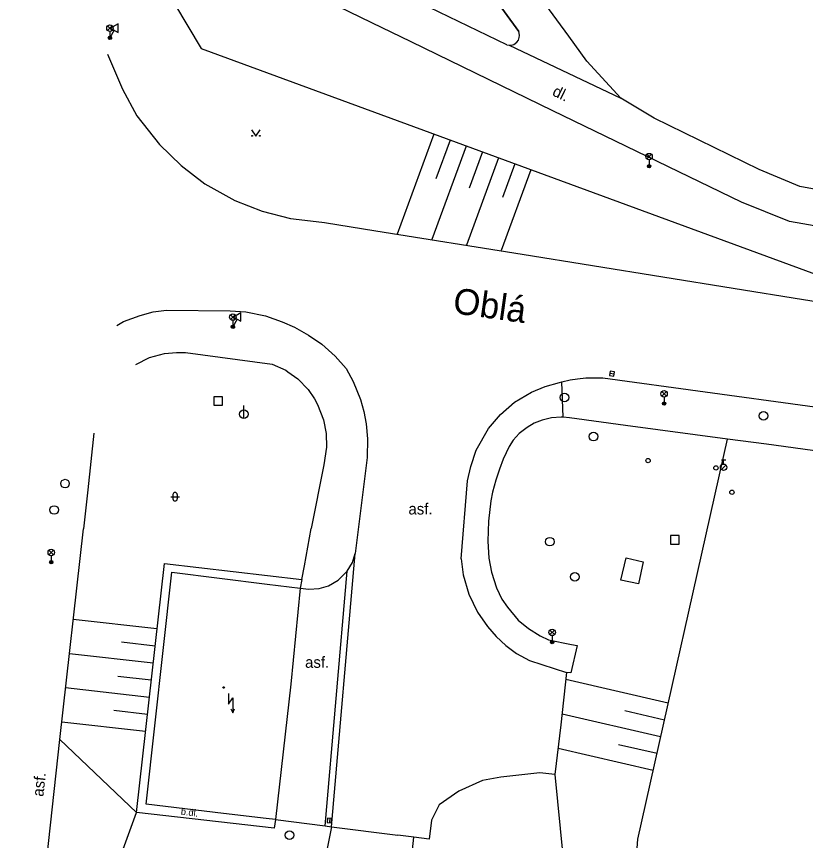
# Model space of a CAD drawing. Extents: x -602419 to -601554, y -1162937 to -1162362.
# Drawn here: x -602029.87 to -601984.03, y -1162678.29 to -1162630.44 of the extents above; entities that cross this region are included whole.
import ezdxf

# ---------------------------------------------------------------- set-up
doc = ezdxf.new("R2010")
doc.units = 0
doc.layers.add('Podklad', color=7, linetype='Continuous')

msp = doc.modelspace()

# ---------------------------------------------------------------- linework, layer by layer
at = {"layer": 'Podklad'}
for p, q in [((-602024.5725, -1162631.25), (-602024.3075, -1162630.985)), ((-602024.5725, -1162630.985), (-602024.3075, -1162631.25)), ((-602024.1855, -1162631.2392), (-602024.44, -1162631.68)), ((-602024.44, -1162631.305), (-602024.44, -1162631.68)), ((-602024.5483, -1162631.6175), (-602024.3317, -1162631.7425)), ((-601993.2525, -1162638.71), (-601992.9875, -1162638.445)), ((-601993.2525, -1162638.445), (-601992.9875, -1162638.71)), ((-601993.12, -1162638.765), (-601993.12, -1162639.14)), ((-602017.4325, -1162648.03), (-602017.1675, -1162647.765)), ((-602017.4325, -1162647.765), (-602017.1675, -1162648.03)), ((-602017.0455, -1162648.0192), (-602017.3, -1162648.46)), ((-602017.3, -1162648.085), (-602017.3, -1162648.46)), ((-602017.4083, -1162648.3975), (-602017.1917, -1162648.5225)), ((-601995.3937, -1162651.1622), (-601995.1463, -1162651.1978)), ((-601992.3825, -1162652.49), (-601992.1175, -1162652.225)), ((-601992.3825, -1162652.225), (-601992.1175, -1162652.49)), ((-601992.25, -1162652.545), (-601992.25, -1162652.92)), ((-602016.6599, -1162653.78), (-602016.6599, -1162653.03)), ((-602025.38, -1162654.64), (-602025.7199, -1162657.93)), ((-601988.915, -1162656.1825), (-601988.665, -1162656.1825)), ((-601988.79, -1162656.4325), (-601988.79, -1162656.1825)), ((-601988.919, -1162656.756), (-601988.654, -1162656.491)), ((-602020.903, -1162658.328), (-602020.403, -1162658.328)), ((-602020.778, -1162658.203), (-602020.778, -1162658.453)), ((-602020.528, -1162658.203), (-602020.528, -1162658.453)), ((-602027.9825, -1162661.7), (-602027.7175, -1162661.435)), ((-602027.9825, -1162661.435), (-602027.7175, -1162661.7)), ((-602027.85, -1162661.755), (-602027.85, -1162662.13)), ((-601998.8825, -1162666.34), (-601998.6175, -1162666.075)), ((-601998.8825, -1162666.075), (-601998.6175, -1162666.34)), ((-601998.75, -1162666.395), (-601998.75, -1162666.77)), ((-602011.6708, -1162677.0053), (-602011.6892, -1162677.2547))]:
    msp.add_line(p, q, dxfattribs=at)
for points in [[(-602024.45, -1162623.4), (-602019.15, -1162632.31), (-601975.87, -1162648.2)], [(-602009.2199, -1162630.81), (-602022.88, -1162624.18)], [(-602000.69, -1162631.32), (-602003.71, -1162627.1599)], [(-602003.71, -1162627.1599), (-602000.69, -1162631.32)], [(-601997.78, -1162631.59), (-602000.3, -1162628.14)], [(-602001.39, -1162632.08), (-602006.44, -1162629.65)], [(-602006.94, -1162631.92), (-602009.2199, -1162630.81)], [(-602001.39, -1162632.08), (-602001.25, -1162632.11), (-602001.11, -1162632.1), (-602000.9699, -1162632.06), (-602000.8, -1162631.93), (-602000.71, -1162631.81), (-602000.6599, -1162631.67), (-602000.64, -1162631.55), (-602000.6599, -1162631.4099), (-602000.69, -1162631.32)], [(-601998.71, -1162635.92), (-602006.94, -1162631.92)], [(-601982.56, -1162640.65), (-601984.36, -1162640.32), (-601986.73, -1162639.33), (-601992.83, -1162636.34), (-601994.76, -1162635.18), (-601996.73, -1162633.03), (-601997.78, -1162631.59)], [(-602001.25, -1162632.11), (-601994.76, -1162635.18)], [(-602024.58, -1162632.64), (-602023.7199, -1162634.6599), (-602022.88, -1162636.21), (-602021.56, -1162637.87), (-602020.31, -1162639.1), (-602018.92, -1162640.17), (-602017.19, -1162641.12), (-602015.6, -1162641.74), (-602013.95, -1162642.17), (-602012.46, -1162642.35), (-602011.9699, -1162642.4)], [(-601983.08, -1162642.68), (-601984.96, -1162642.34), (-601987.76, -1162641.23), (-601998.71, -1162635.92)], [(-602016.21, -1162637.025), (-602015.96, -1162637.4), (-602015.71, -1162637.025)], [(-602005.62, -1162637.28), (-602007.75, -1162643.08)], [(-602004.68, -1162637.62), (-602005.5, -1162639.87)], [(-602003.74, -1162637.9699), (-602005.74, -1162643.4)], [(-602001.86, -1162638.6599), (-602003.7199, -1162643.7199)], [(-602002.8, -1162638.31), (-602003.57, -1162640.4099)], [(-602000.92, -1162639), (-602001.64, -1162640.95)], [(-601999.99, -1162639.35), (-602001.71, -1162644.04)], [(-602011.9699, -1162642.4), (-602009, -1162642.88)], [(-602009, -1162642.88), (-602000.49, -1162644.24)], [(-602000.49, -1162644.24), (-601984.15, -1162646.87)], [(-601984.15, -1162646.87), (-601975.87, -1162648.2)], [(-602024.04, -1162648.38), (-602023.6599, -1162648.15), (-602022.69, -1162647.8), (-602021.92, -1162647.6), (-602021.1599, -1162647.5)], [(-602021.1599, -1162647.5), (-602017.45, -1162647.54)], [(-602017.45, -1162647.54), (-602016.55, -1162647.6), (-602015.4099, -1162647.83), (-602014.43, -1162648.18), (-602013.7199, -1162648.49), (-602013.4569, -1162648.6343), (-602012.9, -1162648.94), (-602012.13, -1162649.48), (-602011.35, -1162650.17), (-602010.71, -1162650.89), (-602010.31, -1162651.63), (-602009.89, -1162652.68), (-602009.7, -1162653.38), (-602009.56, -1162654.09), (-602009.4699, -1162654.96), (-602009.5, -1162656.06)], [(-602022.93, -1162650.65), (-602022.15, -1162650.24), (-602021.28, -1162650.01), (-602020.58, -1162649.95), (-602020.05, -1162649.96)], [(-602020.05, -1162649.96), (-602015.02, -1162650.63)], [(-602015.02, -1162650.63), (-602014.23, -1162650.99), (-602014.108, -1162651.0771), (-602013.53, -1162651.49), (-602012.92, -1162652.11), (-602012.55, -1162652.64), (-602012.39, -1162652.9699), (-602012.04, -1162653.87), (-602011.87, -1162654.65), (-602011.86, -1162655.46), (-602012.02, -1162656.4699)], [(-602003.6599, -1162657.4099), (-602003.48, -1162656.57), (-602003.17, -1162655.62), (-602002.45, -1162654.37), (-602001.75, -1162653.55), (-602000.94, -1162652.84), (-601999.96, -1162652.26), (-601999.1599, -1162651.93), (-601998.33, -1162651.7), (-601998.1862, -1162651.6658), (-601997.7, -1162651.55), (-601997.2688, -1162651.4884), (-601996.79, -1162651.42), (-601995.8, -1162651.42)], [(-601995.8, -1162651.42), (-601983.9133, -1162653.0562), (-601972.9094, -1162654.571)], [(-601998.1199, -1162653.7185), (-601998.1862, -1162651.6658)], [(-601997.75, -1162653.75), (-601998.1199, -1162653.7185), (-601998.2199, -1162653.71), (-601998.79, -1162653.75), (-601999.33, -1162653.89), (-601999.79, -1162654.06), (-602000.21, -1162654.31), (-602000.6599, -1162654.6599), (-602001.01, -1162655.05), (-602001.25, -1162655.4099), (-602001.59, -1162656.15), (-602001.81, -1162656.73), (-602002.02, -1162657.36), (-602002.21, -1162658.07), (-602002.31, -1162658.57), (-602002.45, -1162659.74), (-602002.48, -1162660.92), (-602002.42, -1162661.9), (-602002.28, -1162662.7199), (-602001.99, -1162663.63), (-602001.67, -1162664.27), (-602001.35, -1162664.75), (-602000.73, -1162665.49), (-602000.12, -1162665.98), (-601999.45, -1162666.4), (-601998.96, -1162666.64)], [(-601988.57, -1162654.98), (-601994.49, -1162654.19), (-601997.75, -1162653.75)], [(-601928.54, -1162694.32), (-601947.71, -1162697.88), (-601984.32, -1162697.95), (-601986.89, -1162696.1), (-601988.58, -1162694.52), (-601989.65, -1162693.28), (-601989.95, -1162692.89), (-601990.81, -1162691.65), (-601991.85, -1162689.83), (-601993.05, -1162686.96), (-601993.69, -1162684.25), (-601993.99, -1162681.09), (-601993.78, -1162678.2199), (-601988.57, -1162654.98)], [(-601986.29, -1162655.28), (-601988.57, -1162654.98)], [(-601983.0609, -1162655.7135), (-601986.29, -1162655.28)], [(-602009.5, -1162656.06), (-602010.19, -1162661.62)], [(-602012.02, -1162656.4699), (-602012.75, -1162660.18)], [(-602004.04, -1162661.93), (-602003.6599, -1162657.4099)], [(-602025.7199, -1162657.93), (-602025.98, -1162660.19)], [(-602027.35, -1162672.42), (-602025.98, -1162660.19)], [(-602013.14, -1162662.35), (-602012.75, -1162660.18)], [(-602011.56, -1162677.49), (-602010.19, -1162661.62)], [(-602010.65, -1162662.65), (-602010.35, -1162662.14), (-602010.19, -1162661.62)], [(-602004.04, -1162661.93), (-602003.92, -1162662.87), (-602003.59, -1162663.99), (-602003.08, -1162665.03), (-602002.51, -1162665.86), (-602002, -1162666.44), (-602001.44, -1162666.9699), (-602000.82, -1162667.43), (-602000.07, -1162667.85)], [(-601994.46, -1162661.87), (-601993.46, -1162662.11), (-601993.73, -1162663.39), (-601994.76, -1162663.17), (-601994.46, -1162661.87)], [(-602022.9, -1162676.6599), (-602021.28, -1162662.2), (-602013.3, -1162663.14)], [(-602013.3, -1162663.14), (-602013.14, -1162662.35)], [(-602022.34, -1162676.19), (-602020.84, -1162662.7199)], [(-602020.84, -1162662.7199), (-602015.3, -1162663.4)], [(-602013.38, -1162663.64), (-602012.89, -1162663.7), (-602012.28, -1162663.6599), (-602011.74, -1162663.5), (-602011.18, -1162663.18), (-602010.65, -1162662.65)], [(-602011.93, -1162677.44), (-602010.65, -1162662.65)], [(-602015.3, -1162663.4), (-602013.38, -1162663.64)], [(-602013.3, -1162663.14), (-602013.38, -1162663.64)], [(-602013.38, -1162663.64), (-602013.94, -1162669.21)], [(-602021.71, -1162666), (-602026.57, -1162665.46)], [(-602021.82, -1162667), (-602023.76, -1162666.78)], [(-601998.96, -1162666.64), (-601997.62, -1162666.9099), (-601997.3, -1162666.9699), (-601997.6599, -1162668.56), (-601997.9099, -1162668.53)], [(-602021.93, -1162667.99), (-602026.79, -1162667.45)], [(-602000.07, -1162667.85), (-601997.9099, -1162668.53)], [(-602022.04, -1162668.98), (-602023.99, -1162668.77)], [(-601997.9099, -1162668.53), (-601998.24, -1162671.58), (-601998.59, -1162674.46)], [(-602013.94, -1162669.21), (-602014.83, -1162677.07)], [(-601992.01, -1162670.32), (-601997.95, -1162668.95)], [(-602022.15, -1162669.98), (-602027.02, -1162669.43)], [(-602017.56, -1162669.76), (-602017.56, -1162670.385), (-602017.31, -1162670.01), (-602017.31, -1162670.885)], [(-602022.26, -1162670.9699), (-602024.21, -1162670.75)], [(-602017.4195, -1162670.6405), (-602017.31, -1162670.885), (-602017.2005, -1162670.6405)], [(-601992.23, -1162671.3), (-601994.53, -1162670.76)], [(-601992.45, -1162672.27), (-601998.17, -1162670.95)], [(-602022.37, -1162671.9699), (-602027.24, -1162671.42)], [(-602029.87, -1162695.42), (-602028.77, -1162685.4), (-602027.35, -1162672.42)], [(-602027.35, -1162672.42), (-602022.9, -1162676.6599)], [(-601992.88, -1162674.2199), (-601998.4099, -1162672.95)], [(-601992.6599, -1162673.24), (-601994.89, -1162672.73)], [(-601998.59, -1162674.46), (-601999.46, -1162674.36), (-602001.74, -1162674.62), (-602002.79, -1162674.8), (-602004.18, -1162675.42), (-602005.31, -1162676.23), (-602005.76, -1162677.11), (-602005.9, -1162678.21), (-602006.7841, -1162678.0983), (-602007.7199, -1162677.98)], [(-601998.59, -1162674.46), (-601997.1599, -1162688.95), (-601990.98, -1162701.28)], [(-602017.84, -1162676.7199), (-602022.34, -1162676.19)], [(-602021.77, -1162698.83), (-602022.75, -1162698.11), (-602023.56, -1162695.49), (-602024, -1162693.13), (-602023.97, -1162689.98), (-602025.58, -1162684.06), (-602022.9, -1162676.66)], [(-602014.83, -1162677.07), (-602014.9, -1162677.58), (-602022.9, -1162676.6599)], [(-602015.37, -1162677.01), (-602017.84, -1162676.7199)], [(-602014.83, -1162677.07), (-602015.37, -1162677.01)], [(-602014.83, -1162677.07), (-602011.93, -1162677.44)], [(-602011.93, -1162677.44), (-602011.56, -1162677.49)], [(-602011.56, -1162677.49), (-602013.02, -1162684.72)], [(-602011.56, -1162677.49), (-602007.7199, -1162677.98)], [(-602007.5488, -1162685.3648), (-602007.533, -1162685.2149), (-602006.7841, -1162678.0983)]]:
    msp.add_lwpolyline(points, dxfattribs=at)
for points in [[(-602024.402, -1162631.1142), (-602023.969, -1162631.3642), (-602023.969, -1162630.8642)], [(-602017.262, -1162647.8942), (-602016.829, -1162648.1442), (-602016.829, -1162647.6442)], [(-601995.4115, -1162651.2859), (-601995.1641, -1162651.3215), (-601995.1285, -1162651.0741), (-601995.3759, -1162651.0385)], [(-602018.4, -1162653.02), (-602017.9, -1162653.02), (-602017.9, -1162652.52), (-602018.4, -1162652.52)], [(-601991.88, -1162661.08), (-601991.38, -1162661.08), (-601991.38, -1162660.58), (-601991.88, -1162660.58)], [(-602011.7955, -1162676.9962), (-602011.8138, -1162677.2455), (-602011.5645, -1162677.2638), (-602011.5462, -1162677.0145)]]:
    msp.add_lwpolyline(points, close=True, dxfattribs=at)
for centre, radius in [((-602024.44, -1162631.1175), 0.1875), ((-602024.44, -1162631.68), 0.1), ((-602024.44, -1162631.68), 0.0723), ((-602024.44, -1162631.68), 0.0438), ((-602016.1851, -1162637.3749), 0.025), ((-602015.7354, -1162637.3749), 0.025), ((-601993.12, -1162638.5775), 0.1875), ((-601993.12, -1162639.14), 0.1), ((-601993.12, -1162639.14), 0.0723), ((-601993.12, -1162639.14), 0.0438), ((-602017.3, -1162647.8975), 0.1875), ((-602017.3, -1162648.46), 0.1), ((-602017.3, -1162648.46), 0.0723), ((-602017.3, -1162648.46), 0.0438), ((-601998.03, -1162652.57), 0.25), ((-601992.25, -1162652.3575), 0.1875), ((-601992.25, -1162652.92), 0.1), ((-601992.25, -1162652.92), 0.0723), ((-601992.25, -1162652.92), 0.0438), ((-602016.6599, -1162653.53), 0.25), ((-601986.48, -1162653.63), 0.25), ((-601996.35, -1162654.84), 0.25), ((-601993.18, -1162656.23), 0.125), ((-601989.24, -1162656.6599), 0.125), ((-601988.79, -1162656.62), 0.1875), ((-602027.05, -1162657.57), 0.25), ((-601988.31, -1162658.07), 0.125), ((-602027.68, -1162659.1), 0.25), ((-601998.88, -1162660.94), 0.25), ((-602027.85, -1162661.5675), 0.1875), ((-602027.85, -1162662.13), 0.1), ((-602027.85, -1162662.13), 0.0723), ((-602027.85, -1162662.13), 0.0438), ((-601997.43, -1162662.98), 0.25), ((-601998.75, -1162666.2075), 0.1875), ((-601998.75, -1162666.77), 0.1), ((-601998.75, -1162666.77), 0.0723), ((-601998.75, -1162666.77), 0.0438), ((-602017.83, -1162669.4099), 0.045), ((-602017.83, -1162669.4099), 0.0199), ((-602014.01, -1162677.98), 0.25)]:
    msp.add_circle(centre, radius, dxfattribs=at)
for centre, start, end in [((-602020.6528, -1162658.2031), 0, 180), ((-602020.6528, -1162658.4531), 180, 0)]:
    msp.add_arc(centre, 0.125, start, end, dxfattribs=at)

# ---------------------------------------------------------------- texts
for s, height, rotation, p in [('dl.', 0.65, 334.07, (-601998.79, -1162635)), ('Oblá', 1.5, 352.06, (-602004.5687, -1162647.6628)), ('asf.', 0.65, 83.67, (-602028.31, -1162675.77)), ('b.dl.', 0.4, 353.08108, (-602020.34, -1162676.79))]:
    msp.add_text(s, height=height, rotation=rotation, dxfattribs=at).set_placement(p)
for p in [(-602007.1, -1162659.362), (-602013.1042, -1162668.2655)]:
    msp.add_text('asf.', height=0.65, dxfattribs=at).set_placement(p)

doc.saveas('drawing.dxf')
